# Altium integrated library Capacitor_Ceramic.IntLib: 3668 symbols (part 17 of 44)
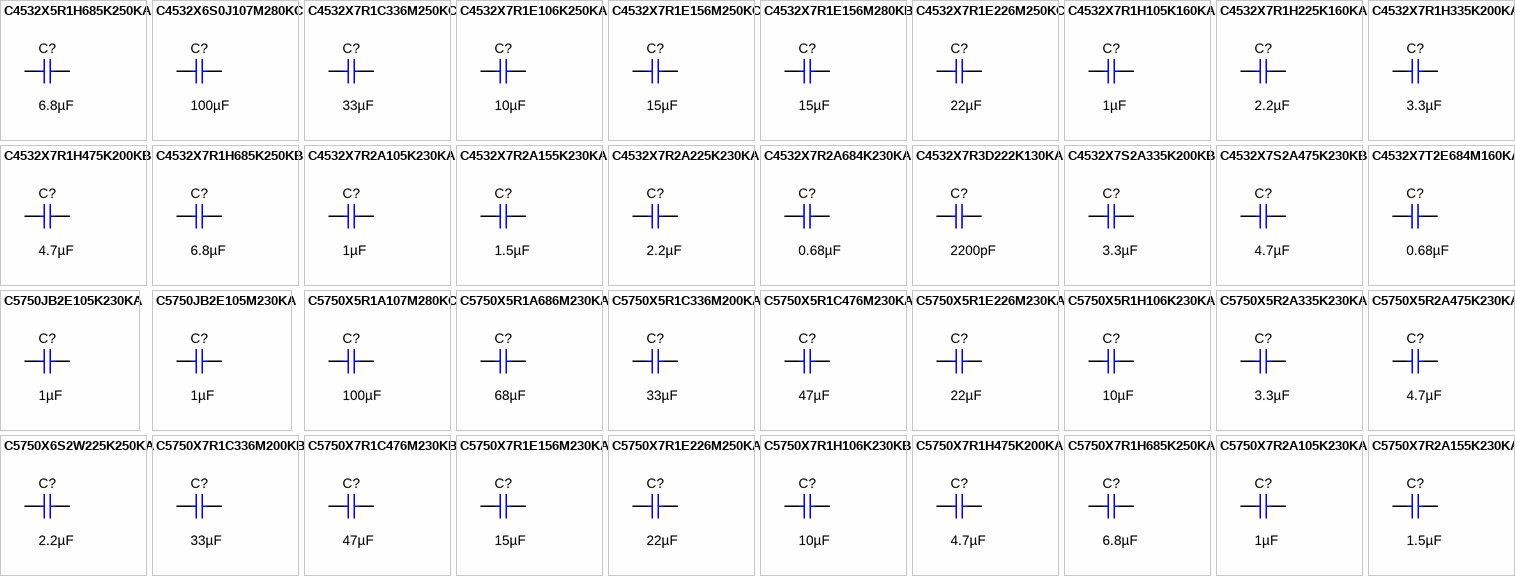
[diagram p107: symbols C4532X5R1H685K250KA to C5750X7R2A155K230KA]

## C4532X7R1E156M280KB
designator C?  ValueDisplayed: 15µF  (hidden comment: C4532X7R1E156M280KB)
CAP, CERM, 15 µF, 25 V,+/- 20%, X7R, 1812; Manufacturer: TDK; Polarized: N; CompType: Capacitor; Value: 15uF; U/M: EA; Cap_F: 0.000015; Tolerance_%: 20; ESR_ohm: 0.002488; Value1: 0.002488 ohm; VDC_V: 25; Value2: 25V; IRMS_A: 4.86254; TaMin_C: -55; TaMax_C: 125; Cap_Case: 1812; SizeArea_mm2: 14.4; SizeAreaWB_mm2: 23.1; SizeX_mm: 4.5; SizeY_mm: 3.2; AEC Category: Q200; Green_Lifecycle: Active; Green_REACh: Passed
signal-integrity model Cap
simulation model Cap
footprint 1812_320
footprint 1812_320M
footprint 1812_320L
pins: 1, 2

## C4532X7R1E226M250KC
designator C?  ValueDisplayed: 22µF  (hidden comment: C4532X7R1E226M250KC)
CAP, CERM, 22 µF, 25 V,+/- 20%, X7R, 1812; Manufacturer: TDK; Polarized: N; CompType: Capacitor; Value: 22uF; U/M: EA; Cap_F: 0.000022; Tolerance_%: 20; ESR_ohm: 0.002434; Value1: 0.002434 ohm; VDC_V: 25; Value2: 25V; IRMS_A: 4.91649; TaMin_C: -55; TaMax_C: 125; Cap_Case: 1812; SizeArea_mm2: 14.4; SizeAreaWB_mm2: 23.1; SizeX_mm: 4.5; SizeY_mm: 3.2; SizeZ_mm: 2.8; AEC Category: Q200; Green_Lifecycle: Active; Green_REACh: Passed
signal-integrity model Cap
simulation model Cap
footprint 1812_280
footprint 1812_280M
footprint 1812_280L
pins: 1, 2

## C4532X7R1H105K160KA
designator C?  ValueDisplayed: 1µF  (hidden comment: C4532X7R1H105K160KA)
CAP, CERM, 1 µF, 50 V,+/- 10%, X7R, 1812; Manufacturer: TDK; Polarized: N; CompType: Capacitor; Value: 1uF; U/M: EA; Cap_F: 0.000001; Tolerance_%: 10; ESR_ohm: 0.007217; Value1: 0.007217 ohm; VDC_V: 50; Value2: 50V; IRMS_A: 2.85919; TaMin_C: -55; TaMax_C: 125; Cap_Case: 1812; SizeArea_mm2: 14.4; SizeAreaWB_mm2: 23.1; SizeX_mm: 4.5; SizeY_mm: 3.2; SizeZ_mm: 1.8; AEC Category: Q200
signal-integrity model Cap
simulation model Cap
footprint 1812_180
pins: 1, 2

## C4532X7R1H225K160KA
designator C?  ValueDisplayed: 2.2µF  (hidden comment: C4532X7R1H225K160KA)
CAP, CERM, 2.2 µF, 50 V,+/- 10%, X7R, 1812; Manufacturer: TDK; Polarized: N; CompType: Capacitor; Value: 2.2uF; U/M: EA; Cap_F: 0.0000022; Tolerance_%: 10; ESR_ohm: 0.00496; Value1: 0.00496 ohm; VDC_V: 50; Value2: 50V; IRMS_A: 3.44575; TaMin_C: -55; TaMax_C: 125; Cap_Case: 1812; SizeArea_mm2: 14.4; SizeAreaWB_mm2: 23.1; SizeX_mm: 4.5; SizeY_mm: 3.2; SizeZ_mm: 1.8; AEC Category: Q200
signal-integrity model Cap
simulation model Cap
footprint 1812_180
pins: 1, 2

## C4532X7R1H335K200KA
designator C?  ValueDisplayed: 3.3µF  (hidden comment: C4532X7R1H335K200KA)
CAP, CERM, 3.3 µF, 50 V,+/- 10%, X7R, 1812; Manufacturer: TDK; Polarized: N; CompType: Capacitor; Value: 3.3uF; U/M: EA; Cap_F: 0.0000033; Tolerance_%: 10; ESR_ohm: 0.004024; Value1: 0.004024 ohm; VDC_V: 50; Value2: 50V; IRMS_A: 3.82481; TaMin_C: -55; TaMax_C: 125; Cap_Case: 1812; SizeArea_mm2: 14.4; SizeAreaWB_mm2: 23.1; SizeX_mm: 4.5; SizeY_mm: 3.2; SizeZ_mm: 2.2; AEC Category: Q200
signal-integrity model Cap
simulation model Cap
footprint 1812_220
footprint 1812_220M
footprint 1812_220L
pins: 1, 2

## C4532X7R1H475K200KB
designator C?  ValueDisplayed: 4.7µF  (hidden comment: C4532X7R1H475K200KB)
CAP, CERM, 4.7 µF, 50 V,+/- 10%, X7R, 1812; Manufacturer: TDK; Polarized: N; CompType: Capacitor; Value: 4.7uF; U/M: EA; Cap_F: 0.0000047; Tolerance_%: 10; ESR_ohm: 0.005172; Value1: 0.005172 ohm; VDC_V: 50; Value2: 50V; IRMS_A: 3.37342; TaMin_C: -55; TaMax_C: 125; Cap_Case: 1812; SizeArea_mm2: 14.4; SizeAreaWB_mm2: 23.1; SizeX_mm: 4.5; SizeY_mm: 3.2; SizeZ_mm: 2.2; AEC Category: Q200; Green_Lifecycle: Active; Green_REACh: Passed
signal-integrity model Cap
simulation model Cap
footprint 1812_220
footprint 1812_220M
footprint 1812_220L
pins: 1, 2

## C4532X7R1H685K250KB
designator C?  ValueDisplayed: 6.8µF  (hidden comment: C4532X7R1H685K250KB)
CAP, CERM, 6.8 µF, 50 V,+/- 10%, X7R, 1812; Manufacturer: TDK; Polarized: N; CompType: Capacitor; Value: 6.8uF; U/M: EA; Cap_F: 0.0000068; Tolerance_%: 10; ESR_ohm: 0.002621; Value1: 0.002621 ohm; VDC_V: 50; Value2: 50V; IRMS_A: 4.73771; TaMin_C: -55; TaMax_C: 125; Cap_Case: 1812; SizeArea_mm2: 14.4; SizeAreaWB_mm2: 23.1; SizeX_mm: 4.5; SizeY_mm: 3.2; SizeZ_mm: 2.8; AEC Category: Q200; Green_Lifecycle: Active; Green_REACh: Passed
signal-integrity model Cap
simulation model Cap
footprint 1812_280
footprint 1812_280M
footprint 1812_280L
pins: 1, 2

## C4532X7R2A105K230KA
designator C?  ValueDisplayed: 1µF  (hidden comment: C4532X7R2A105K230KA)
CAP, CERM, 1 µF, 100 V,+/- 10%, X7R, 1812; Manufacturer: TDK; Polarized: N; CompType: Capacitor; Value: 1uF; U/M: EA; Cap_F: 0.000001; Tolerance_%: 10; ESR_ohm: 0.005865; Value1: 0.005865 ohm; VDC_V: 100; Value2: 100V; IRMS_A: 3.17165; TaMin_C: -55; TaMax_C: 125; Cap_Case: 1812; SizeArea_mm2: 14.4; SizeAreaWB_mm2: 23.1; SizeX_mm: 4.5; SizeY_mm: 3.2; SizeZ_mm: 2.54; AEC Category: Q200
signal-integrity model Cap
simulation model Cap
footprint 1812_254
pins: 1, 2

## C4532X7R2A155K230KA
designator C?  ValueDisplayed: 1.5µF  (hidden comment: C4532X7R2A155K230KA)
CAP, CERM, 1.5 µF, 100 V,+/- 10%, X7R, 1812; Manufacturer: TDK; Polarized: N; CompType: Capacitor; Value: 1.5uF; U/M: EA; Cap_F: 0.0000015; Tolerance_%: 10; ESR_ohm: 0.00449; Value1: 0.00449 ohm; VDC_V: 100; Value2: 100V; IRMS_A: 3.62321; TaMin_C: -55; TaMax_C: 125; Cap_Case: 1812; SizeArea_mm2: 14.4; SizeAreaWB_mm2: 23.1; SizeX_mm: 4.5; SizeY_mm: 3.2; SizeZ_mm: 2.54; AEC Category: Q200
signal-integrity model Cap
simulation model Cap
footprint 1812_254
pins: 1, 2

## C4532X7R2A225K230KA
designator C?  ValueDisplayed: 2.2µF  (hidden comment: C4532X7R2A225K230KA)
CAP, CERM, 2.2 µF, 100 V,+/- 10%, X7R, 1812; Manufacturer: TDK; Polarized: N; CompType: Capacitor; Value: 2.2uF; U/M: EA; Cap_F: 0.0000022; Tolerance_%: 10; ESR_ohm: 0.002981; Value1: 0.002981 ohm; VDC_V: 100; Value2: 100V; IRMS_A: 4.44466; TaMin_C: -55; TaMax_C: 125; Cap_Case: 1812; SizeArea_mm2: 14.4; SizeAreaWB_mm2: 23.1; SizeX_mm: 4.5; SizeY_mm: 3.2; SizeZ_mm: 2.54; AEC Category: Q200; Green_Lifecycle: Active; Green_REACh: Passed
signal-integrity model Cap
simulation model Cap
footprint 1812_254
pins: 1, 2

## C4532X7R2A684K230KA
designator C?  ValueDisplayed: 0.68µF  (hidden comment: C4532X7R2A684K230KA)
CAP, CERM, 0.68 µF, 100 V,+/- 10%, X7R, 1812; Manufacturer: TDK; Polarized: N; CompType: Capacitor; Value: 0.68uF; U/M: EA; Cap_F: 0.00000068; Tolerance_%: 10; ESR_ohm: 0.007113; Value1: 0.007113 ohm; VDC_V: 100; Value2: 100V; IRMS_A: 2.8819; TaMin_C: -55; TaMax_C: 125; Cap_Case: 1812; SizeArea_mm2: 14.4; SizeAreaWB_mm2: 23.1; SizeX_mm: 4.5; SizeY_mm: 3.2; SizeZ_mm: 2.54; AEC Category: Q200
signal-integrity model Cap
simulation model Cap
footprint 1812_254
pins: 1, 2

## C4532X7R3D222K130KA
designator C?  ValueDisplayed: 2200pF  (hidden comment: C4532X7R3D222K130KA)
CAP, CERM, 2200 pF, 2000 V,+/- 10%, X7R, 1812; Manufacturer: TDK; Polarized: N; CompType: Capacitor; Value: 2200pF; U/M: EA; Cap_F: 0.0000000022; Tolerance_%: 10; VDC_V: 2000; Value2: 2000V; TaMin_C: -55; TaMax_C: 125; Cap_Case: 1812; SizeArea_mm2: 14.4; SizeAreaWB_mm2: 23.1; SizeX_mm: 4.5; SizeY_mm: 3.2; SizeZ_mm: 1.35; AEC Category: Q200; Green_Lifecycle: Active; Green_REACh: Passed
signal-integrity model Cap
simulation model Cap
footprint 1812
footprint 1812M
footprint 1812L
footprint 1812_HV
pins: 1, 2

## C4532X7S2A335K200KB
designator C?  ValueDisplayed: 3.3µF  (hidden comment: C4532X7S2A335K200KB)
CAP, CERM, 3.3 µF, 100 V,+/- 10%, X7S, 1812; Manufacturer: TDK; Polarized: N; CompType: Capacitor; Value: 3.3uF; U/M: EA; Cap_F: 0.0000033; Tolerance_%: 10; ESR_ohm: 0.004622; Value1: 0.004622 ohm; VDC_V: 100; Value2: 100V; IRMS_A: 3.5689; TaMin_C: -55; TaMax_C: 125; Cap_Case: 1812; SizeArea_mm2: 14.4; SizeAreaWB_mm2: 23.1; SizeX_mm: 4.5; SizeY_mm: 3.2; SizeZ_mm: 2.2; AEC Category: Q200
signal-integrity model Cap
simulation model Cap
footprint 1812_220
footprint 1812_220M
footprint 1812_220L
pins: 1, 2

## C4532X7S2A475K230KB
designator C?  ValueDisplayed: 4.7µF  (hidden comment: C4532X7S2A475K230KB)
CAP, CERM, 4.7 µF, 100 V,+/- 10%, X7S, 1812; Manufacturer: TDK; Polarized: N; CompType: Capacitor; Value: 4.7uF; U/M: EA; Cap_F: 0.0000047; Tolerance_%: 10; ESR_ohm: 0.00515; Value1: 0.00515 ohm; VDC_V: 100; Value2: 100V; IRMS_A: 3.38056; TaMin_C: -55; TaMax_C: 125; Cap_Case: 1812; SizeArea_mm2: 14.4; SizeAreaWB_mm2: 23.1; SizeX_mm: 4.5; SizeY_mm: 3.2; SizeZ_mm: 2.54; AEC Category: Q200
signal-integrity model Cap
simulation model Cap
footprint 1812_254
pins: 1, 2

## C4532X7T2E684M160KA
designator C?  ValueDisplayed: 0.68µF  (hidden comment: C4532X7T2E684M160KA)
CAP, CERM, 0.68 µF, 250 V,+/- 20%, X7T, 1812; Manufacturer: TDK; Polarized: N; CompType: Capacitor; Value: 0.68uF; U/M: EA; Cap_F: 0.00000068; Tolerance_%: 20; VDC_V: 250; Value2: 250V; TaMin_C: -55; TaMax_C: 125; Cap_Case: 1812; SizeArea_mm2: 14.4; SizeAreaWB_mm2: 23.1; SizeX_mm: 4.5; SizeY_mm: 3.2; SizeZ_mm: 1.35; AEC Category: Q200
signal-integrity model Cap
simulation model Cap
footprint 1812
footprint 1812M
footprint 1812L
footprint 1812_HV
pins: 1, 2

## C5750JB2E105K230KA
designator C?  ValueDisplayed: 1µF  (hidden comment: C5750JB2E105K230KA)
CAP, CERM, 1 µF, 250 V,+/- 10%, JB, 2220; Manufacturer: TDK; Polarized: N; CompType: Capacitor; Value: 1uF; U/M: EA; Cap_F: 0.000001; Tolerance_%: 10; VDC_V: 250; Value2: 250V; TaMin_C: -25; TaMax_C: 85; Cap_Case: 2220; SizeArea_mm2: 28.5; SizeAreaWB_mm2: 53.9; SizeX_mm: 5.7; SizeY_mm: 5; SizeZ_mm: 2.5; AEC Category: Q200; Green_Lifecycle: Not Set; Green_REACh: Incomplete
signal-integrity model Cap
simulation model Cap
footprint 2220_250
footprint 2220_250M
footprint 2220_250L
pins: 1, 2

## C5750JB2E105M230KA
designator C?  ValueDisplayed: 1µF  (hidden comment: C5750JB2E105M230KA)
CAP, CERM, 1 µF, 250 V,+/- 20%, JB, 2220; Manufacturer: TDK; Polarized: N; CompType: Capacitor; Value: 1uF; U/M: EA; Cap_F: 0.000001; Tolerance_%: 20; VDC_V: 250; Value2: 250V; TaMin_C: -25; TaMax_C: 85; Cap_Case: 2220; SizeArea_mm2: 28.5; SizeAreaWB_mm2: 53.9; SizeX_mm: 5.7; SizeY_mm: 5; SizeZ_mm: 2.5; AEC Category: Q200; Green_Lifecycle: Not Set; Green_REACh: Incomplete
signal-integrity model Cap
simulation model Cap
footprint 2220_250
footprint 2220_250M
footprint 2220_250L
pins: 1, 2

## C5750X5R1A107M280KC
designator C?  ValueDisplayed: 100µF  (hidden comment: C5750X5R1A107M280KC)
CAP, CERM, 100 µF, 10 V,+/- 20%, X5R, 2220; Manufacturer: TDK; Polarized: N; CompType: Capacitor; Value: 100uF; U/M: EA; Cap_F: 0.0001; Tolerance_%: 20; ESR_ohm: 0.004556; Value1: 0.004556 ohm; VDC_V: 10; Value2: 10V; IRMS_A: 4.27708; TaMin_C: -55; TaMax_C: 85; Cap_Case: 2220; SizeArea_mm2: 28.5; SizeAreaWB_mm2: 53.9; SizeX_mm: 5.7; SizeY_mm: 5; SizeZ_mm: 3.1; AEC Category: Q200
signal-integrity model Cap
simulation model Cap
footprint 2220_310
footprint 2220_310M
footprint 2220_310L
pins: 1, 2

## C5750X5R1A686M230KA
designator C?  ValueDisplayed: 68µF  (hidden comment: C5750X5R1A686M230KA)
CAP, CERM, 68 µF, 10 V,+/- 20%, X5R, 2220; Manufacturer: TDK; Polarized: N; CompType: Capacitor; Value: 68uF; U/M: EA; Cap_F: 0.000068; Tolerance_%: 20; ESR_ohm: 0.006828; Value1: 0.006828 ohm; VDC_V: 10; Value2: 10V; IRMS_A: 3.49389; TaMin_C: -55; TaMax_C: 85; Cap_Case: 2220; SizeArea_mm2: 28.5; SizeAreaWB_mm2: 53.9; SizeX_mm: 5.7; SizeY_mm: 5; SizeZ_mm: 2.5; AEC Category: Q200
signal-integrity model Cap
simulation model Cap
footprint 2220_250
footprint 2220_250M
footprint 2220_250L
pins: 1, 2

## C5750X5R1C336M200KA
designator C?  ValueDisplayed: 33µF  (hidden comment: C5750X5R1C336M200KA)
CAP, CERM, 33 µF, 16 V,+/- 20%, X5R, 2220; Manufacturer: TDK; Polarized: N; CompType: Capacitor; Value: 33uF; U/M: EA; Cap_F: 0.000033; Tolerance_%: 20; ESR_ohm: 0.002118; Value1: 0.002118 ohm; VDC_V: 16; Value2: 16V; IRMS_A: 6.27268; TaMin_C: -55; TaMax_C: 85; Cap_Case: 2220; SizeArea_mm2: 28.5; SizeAreaWB_mm2: 53.9; SizeX_mm: 5.7; SizeY_mm: 5; SizeZ_mm: 2.2; AEC Category: Q200
signal-integrity model Cap
simulation model Cap
footprint 2220_220
footprint 2220_220M
footprint 2220_220L
pins: 1, 2

## C5750X5R1C476M230KA
designator C?  ValueDisplayed: 47µF  (hidden comment: C5750X5R1C476M230KA)
CAP, CERM, 47 µF, 16 V,+/- 20%, X5R, 2220; Manufacturer: TDK; Polarized: N; CompType: Capacitor; Value: 47uF; U/M: EA; Cap_F: 0.000047; Tolerance_%: 20; ESR_ohm: 0.003162; Value1: 0.003162 ohm; VDC_V: 16; Value2: 16V; IRMS_A: 5.13436; TaMin_C: -55; TaMax_C: 85; Cap_Case: 2220; SizeArea_mm2: 28.5; SizeAreaWB_mm2: 53.9; SizeX_mm: 5.7; SizeY_mm: 5; SizeZ_mm: 2.5; AEC Category: Q200
signal-integrity model Cap
simulation model Cap
footprint 2220_250
footprint 2220_250M
footprint 2220_250L
pins: 1, 2

## C5750X5R1E226M230KA
designator C?  ValueDisplayed: 22µF  (hidden comment: C5750X5R1E226M230KA)
CAP, CERM, 22 µF, 25 V,+/- 20%, X5R, 2220; Manufacturer: TDK; Polarized: N; CompType: Capacitor; Value: 22uF; U/M: EA; Cap_F: 0.000022; Tolerance_%: 20; ESR_ohm: 0.00305; Value1: 0.00305 ohm; VDC_V: 25; Value2: 25V; IRMS_A: 5.22772; TaMin_C: -55; TaMax_C: 85; Cap_Case: 2220; SizeArea_mm2: 28.5; SizeAreaWB_mm2: 53.9; SizeX_mm: 5.7; SizeY_mm: 5; SizeZ_mm: 2.5; AEC Category: Q200
signal-integrity model Cap
simulation model Cap
footprint 2220_250
footprint 2220_250M
footprint 2220_250L
pins: 1, 2

## C5750X5R1H106K230KA
designator C?  ValueDisplayed: 10µF  (hidden comment: C5750X5R1H106K230KA)
CAP, CERM, 10 µF, 50 V,+/- 10%, X5R, 2220; Manufacturer: TDK; Polarized: N; CompType: Capacitor; Value: 10uF; U/M: EA; Cap_F: 0.00001; Tolerance_%: 10; ESR_ohm: 0.002611; Value1: 0.002611 ohm; VDC_V: 50; Value2: 50V; IRMS_A: 5.65008; TaMin_C: -55; TaMax_C: 85; Cap_Case: 2220; SizeArea_mm2: 28.5; SizeAreaWB_mm2: 53.9; SizeX_mm: 5.7; SizeY_mm: 5; SizeZ_mm: 2.5; AEC Category: Q200
signal-integrity model Cap
simulation model Cap
footprint 2220_250
footprint 2220_250M
footprint 2220_250L
pins: 1, 2

## C5750X5R2A335K230KA
designator C?  ValueDisplayed: 3.3µF  (hidden comment: C5750X5R2A335K230KA)
CAP, CERM, 3.3 µF, 100 V,+/- 10%, X5R, 2220; Manufacturer: TDK; Polarized: N; CompType: Capacitor; Value: 3.3uF; U/M: EA; Cap_F: 0.0000033; Tolerance_%: 10; ESR_ohm: 0.002585; Value1: 0.002585 ohm; VDC_V: 100; Value2: 100V; IRMS_A: 5.68031; TaMin_C: -55; TaMax_C: 85; Cap_Case: 2220; SizeArea_mm2: 28.5; SizeAreaWB_mm2: 53.9; SizeX_mm: 5.7; SizeY_mm: 5; SizeZ_mm: 2.5; AEC Category: Q200
signal-integrity model Cap
simulation model Cap
footprint 2220_250
footprint 2220_250M
footprint 2220_250L
pins: 1, 2

## C5750X5R2A475K230KA
designator C?  ValueDisplayed: 4.7µF  (hidden comment: C5750X5R2A475K230KA)
CAP, CERM, 4.7 µF, 100 V,+/- 10%, X5R, 2220; Manufacturer: TDK; Polarized: N; CompType: Capacitor; Value: 4.7uF; U/M: EA; Cap_F: 0.0000047; Tolerance_%: 10; ESR_ohm: 0.002349; Value1: 0.002349 ohm; VDC_V: 100; Value2: 100V; IRMS_A: 5.95718; TaMin_C: -55; TaMax_C: 85; Cap_Case: 2220; SizeArea_mm2: 28.5; SizeAreaWB_mm2: 53.9; SizeX_mm: 5.7; SizeY_mm: 5; SizeZ_mm: 2.5; AEC Category: Q200
signal-integrity model Cap
simulation model Cap
footprint 2220_250
footprint 2220_250M
footprint 2220_250L
pins: 1, 2

## C5750X6S2W225K250KA
designator C?  ValueDisplayed: 2.2µF  (hidden comment: C5750X6S2W225K250KA)
CAP, CERM, 2.2 µF, 450 V,+/- 10%, X6S, 2220; Manufacturer: TDK; Polarized: N; CompType: Capacitor; Value: 2.2uF; U/M: EA; Cap_F: 0.0000022; Tolerance_%: 10; VDC_V: 450; Value2: 450V; TaMin_C: -55; TaMax_C: 105; Cap_Case: 2220; SizeArea_mm2: 28.5; SizeAreaWB_mm2: 53.9; SizeX_mm: 5.7; SizeY_mm: 5; SizeZ_mm: 2.8; AEC Category: Q200; Green_Lifecycle: Not Set; Green_REACh: Incomplete
signal-integrity model Cap
simulation model Cap
footprint 2220_280
footprint 2220_280M
footprint 2220_280L
pins: 1, 2

## C5750X7R1C336M200KB
designator C?  ValueDisplayed: 33µF  (hidden comment: C5750X7R1C336M200KB)
CAP, CERM, 33 µF, 16 V,+/- 20%, X7R, 2220; Manufacturer: TDK; Polarized: N; CompType: Capacitor; Value: 33uF; U/M: EA; Cap_F: 0.000033; Tolerance_%: 20; ESR_ohm: 0.002118; Value1: 0.002118 ohm; VDC_V: 16; Value2: 16V; IRMS_A: 6.27268; TaMin_C: -55; TaMax_C: 125; Cap_Case: 2220; SizeArea_mm2: 28.5; SizeAreaWB_mm2: 53.9; SizeX_mm: 5.7; SizeY_mm: 5; SizeZ_mm: 2.2; AEC Category: Q200
signal-integrity model Cap
simulation model Cap
footprint 2220_220
footprint 2220_220M
footprint 2220_220L
pins: 1, 2

## C5750X7R1C476M230KB
designator C?  ValueDisplayed: 47µF  (hidden comment: C5750X7R1C476M230KB)
CAP, CERM, 47 µF, 16 V,+/- 20%, X7R, 2220; Manufacturer: TDK; Polarized: N; CompType: Capacitor; Value: 47uF; U/M: EA; Cap_F: 0.000047; Tolerance_%: 20; ESR_ohm: 0.003162; Value1: 0.003162 ohm; VDC_V: 16; Value2: 16V; IRMS_A: 5.13436; TaMin_C: -55; TaMax_C: 125; Cap_Case: 2220; SizeArea_mm2: 28.5; SizeAreaWB_mm2: 53.9; SizeX_mm: 5.7; SizeY_mm: 5; SizeZ_mm: 2.5; AEC Category: Q200
signal-integrity model Cap
simulation model Cap
footprint 2220_250
footprint 2220_250M
footprint 2220_250L
pins: 1, 2

## C5750X7R1E156M230KA
designator C?  ValueDisplayed: 15µF  (hidden comment: C5750X7R1E156M230KA)
CAP, CERM, 15 µF, 25 V,+/- 20%, X7R, 2220; Manufacturer: TDK; Polarized: N; CompType: Capacitor; Value: 15uF; U/M: EA; Cap_F: 0.000015; Tolerance_%: 20; ESR_ohm: 0.002725; Value1: 0.002725 ohm; VDC_V: 25; Value2: 25V; IRMS_A: 5.53023; TaMin_C: -55; TaMax_C: 125; Cap_Case: 2220; SizeArea_mm2: 28.5; SizeAreaWB_mm2: 53.9; SizeX_mm: 5.7; SizeY_mm: 5; SizeZ_mm: 2.5; AEC Category: Q200
signal-integrity model Cap
simulation model Cap
footprint 2220_250
footprint 2220_250M
footprint 2220_250L
pins: 1, 2

## C5750X7R1E226M250KA
designator C?  ValueDisplayed: 22µF  (hidden comment: C5750X7R1E226M250KA)
CAP, CERM, 22 µF, 25 V,+/- 20%, X7R, 2220; Manufacturer: TDK; Polarized: N; CompType: Capacitor; Value: 22uF; U/M: EA; Cap_F: 0.000022; Tolerance_%: 20; ESR_ohm: 0.001893; Value1: 0.001893 ohm; VDC_V: 25; Value2: 25V; IRMS_A: 6.63504; TaMin_C: -55; TaMax_C: 125; Cap_Case: 2220; SizeArea_mm2: 28.5; SizeAreaWB_mm2: 53.9; SizeX_mm: 5.7; SizeY_mm: 5; SizeZ_mm: 2.8; AEC Category: Q200
signal-integrity model Cap
simulation model Cap
footprint 2220_280
footprint 2220_280M
footprint 2220_280L
pins: 1, 2

## C5750X7R1H106K230KB
designator C?  ValueDisplayed: 10µF  (hidden comment: C5750X7R1H106K230KB)
CAP, CERM, 10 µF, 50 V,+/- 10%, X7R, 2220; Manufacturer: TDK; Polarized: N; CompType: Capacitor; Value: 10uF; U/M: EA; Cap_F: 0.00001; Tolerance_%: 10; ESR_ohm: 0.002611; Value1: 0.002611 ohm; VDC_V: 50; Value2: 50V; IRMS_A: 5.65008; TaMin_C: -55; TaMax_C: 125; Cap_Case: 2220; SizeArea_mm2: 28.5; SizeAreaWB_mm2: 53.9; SizeX_mm: 5.7; SizeY_mm: 5; SizeZ_mm: 2.5; AEC Category: Q200; Green_Lifecycle: Active; Green_REACh: Passed
signal-integrity model Cap
simulation model Cap
footprint 2220_250
footprint 2220_250M
footprint 2220_250L
pins: 1, 2

## C5750X7R1H475K200KA
designator C?  ValueDisplayed: 4.7µF  (hidden comment: C5750X7R1H475K200KA)
CAP, CERM, 4.7 µF, 50 V,+/- 10%, X7R, 2220; Manufacturer: TDK; Polarized: N; CompType: Capacitor; Value: 4.7uF; U/M: EA; Cap_F: 0.0000047; Tolerance_%: 10; ESR_ohm: 0.003808; Value1: 0.003808 ohm; VDC_V: 50; Value2: 50V; IRMS_A: 4.67908; TaMin_C: -55; TaMax_C: 125; Cap_Case: 2220; SizeArea_mm2: 28.5; SizeAreaWB_mm2: 53.9; SizeX_mm: 5.7; SizeY_mm: 5; SizeZ_mm: 2.2; AEC Category: Q200
signal-integrity model Cap
simulation model Cap
footprint 2220_220
footprint 2220_220M
footprint 2220_220L
pins: 1, 2

## C5750X7R1H685K250KA
designator C?  ValueDisplayed: 6.8µF  (hidden comment: C5750X7R1H685K250KA)
CAP, CERM, 6.8 µF, 50 V,+/- 10%, X7R, 2220; Manufacturer: TDK; Polarized: N; CompType: Capacitor; Value: 6.8uF; U/M: EA; Cap_F: 0.0000068; Tolerance_%: 10; ESR_ohm: 0.002126; Value1: 0.002126 ohm; VDC_V: 50; Value2: 50V; IRMS_A: 6.26198; TaMin_C: -55; TaMax_C: 125; Cap_Case: 2220; SizeArea_mm2: 28.5; SizeAreaWB_mm2: 53.9; SizeX_mm: 5.7; SizeY_mm: 5; SizeZ_mm: 2.8; AEC Category: Q200
signal-integrity model Cap
simulation model Cap
footprint 2220_280
footprint 2220_280M
footprint 2220_280L
pins: 1, 2

## C5750X7R2A105K230KA
designator C?  ValueDisplayed: 1µF  (hidden comment: C5750X7R2A105K230KA)
CAP, CERM, 1 µF, 100 V,+/- 10%, X7R, 2220; Manufacturer: TDK; Polarized: N; CompType: Capacitor; Value: 1uF; U/M: EA; Cap_F: 0.000001; Tolerance_%: 10; ESR_ohm: 0.0056; Value1: 0.0056 ohm; VDC_V: 100; Value2: 100V; IRMS_A: 3.86315; TaMin_C: -55; TaMax_C: 125; Cap_Case: 2220; SizeArea_mm2: 28.5; SizeAreaWB_mm2: 53.9; SizeX_mm: 5.7; SizeY_mm: 5; SizeZ_mm: 2.5; AEC Category: Q200
signal-integrity model Cap
simulation model Cap
footprint 2220_250
footprint 2220_250M
footprint 2220_250L
pins: 1, 2

## C5750X7R2A155K230KA
designator C?  ValueDisplayed: 1.5µF  (hidden comment: C5750X7R2A155K230KA)
CAP, CERM, 1.5 µF, 100 V,+/- 10%, X7R, 2220; Manufacturer: TDK; Polarized: N; CompType: Capacitor; Value: 1.5uF; U/M: EA; Cap_F: 0.0000015; Tolerance_%: 10; ESR_ohm: 0.00441; Value1: 0.00441 ohm; VDC_V: 100; Value2: 100V; IRMS_A: 4.35148; TaMin_C: -55; TaMax_C: 125; Cap_Case: 2220; SizeArea_mm2: 28.5; SizeAreaWB_mm2: 53.9; SizeX_mm: 5.7; SizeY_mm: 5; SizeZ_mm: 2.5; AEC Category: Q200
signal-integrity model Cap
simulation model Cap
footprint 2220_250
footprint 2220_250M
footprint 2220_250L
pins: 1, 2

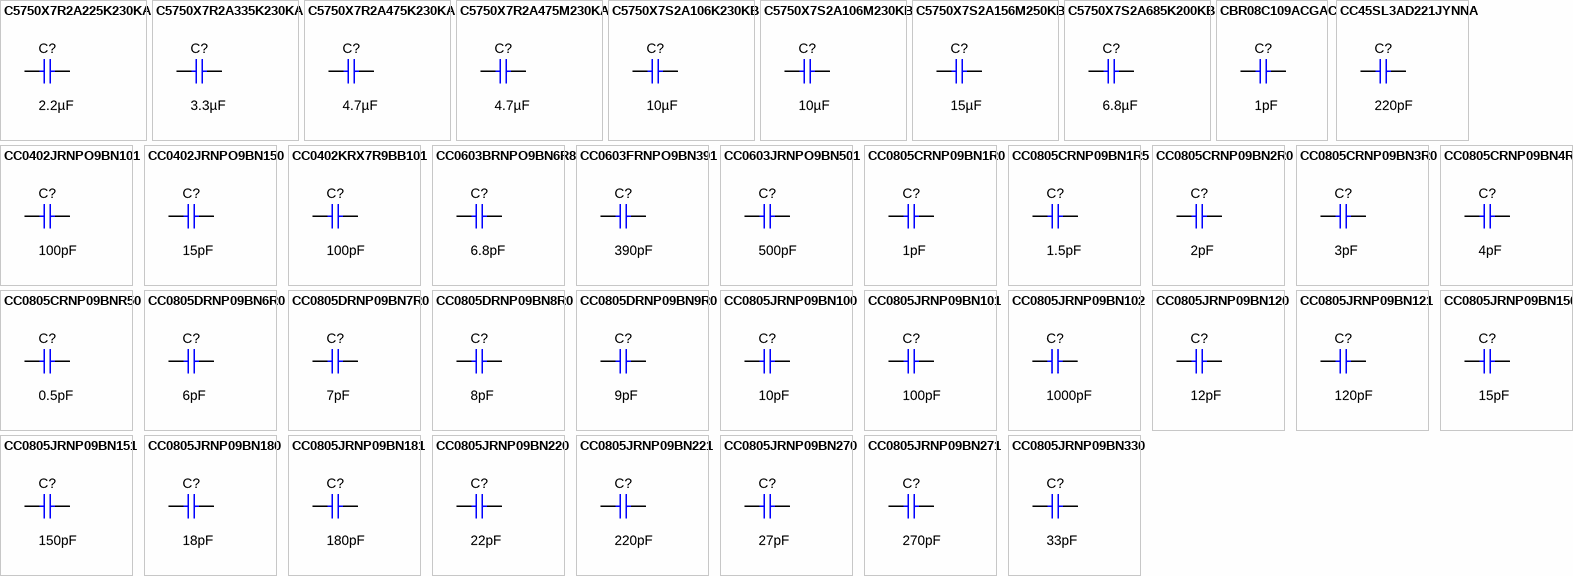
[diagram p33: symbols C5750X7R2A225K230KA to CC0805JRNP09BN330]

## C5750X7R2A225K230KA
designator C?  ValueDisplayed: 2.2µF  (hidden comment: C5750X7R2A225K230KA)
CAP, CERM, 2.2 µF, 100 V,+/- 10%, X7R, 2220; Manufacturer: TDK; Polarized: N; CompType: Capacitor; Value: 2.2uF; U/M: EA; Cap_F: 0.0000022; Tolerance_%: 10; ESR_ohm: 0.002841; Value1: 0.002841 ohm; VDC_V: 100; Value2: 100V; IRMS_A: 5.41912; TaMin_C: -55; TaMax_C: 125; Cap_Case: 2220; SizeArea_mm2: 28.5; SizeAreaWB_mm2: 53.9; SizeX_mm: 5.7; SizeY_mm: 5; SizeZ_mm: 2.5; AEC Category: Q200
signal-integrity model Cap
simulation model Cap
footprint 2220_250
footprint 2220_250M
footprint 2220_250L
pins: 1, 2

## C5750X7R2A335K230KA
designator C?  ValueDisplayed: 3.3µF  (hidden comment: C5750X7R2A335K230KA)
CAP, CERM, 3.3 µF, 100 V,+/- 10%, X7R, 2220; Manufacturer: TDK; Polarized: N; CompType: Capacitor; Value: 3.3uF; U/M: EA; Cap_F: 0.0000033; Tolerance_%: 10; ESR_ohm: 0.002585; Value1: 0.002585 ohm; VDC_V: 100; Value2: 100V; IRMS_A: 5.68031; TaMin_C: -55; TaMax_C: 125; Cap_Case: 2220; SizeArea_mm2: 28.5; SizeAreaWB_mm2: 53.9; SizeX_mm: 5.7; SizeY_mm: 5; SizeZ_mm: 2.5; AEC Category: Q200
signal-integrity model Cap
simulation model Cap
footprint 2220_250
footprint 2220_250M
footprint 2220_250L
pins: 1, 2

## C5750X7R2A475K230KA
designator C?  ValueDisplayed: 4.7µF  (hidden comment: C5750X7R2A475K230KA)
CAP, CERM, 4.7 µF, 100 V,+/- 10%, X7R, 2220; Manufacturer: TDK; Polarized: N; CompType: Capacitor; Value: 4.7uF; U/M: EA; Cap_F: 0.0000047; Tolerance_%: 10; ESR_ohm: 0.002349; Value1: 0.002349 ohm; VDC_V: 100; Value2: 100V; IRMS_A: 5.95718; TaMin_C: -55; TaMax_C: 125; Cap_Case: 2220; SizeArea_mm2: 28.5; SizeAreaWB_mm2: 53.9; SizeX_mm: 5.7; SizeY_mm: 5; SizeZ_mm: 2.5; AEC Category: Q200; Green_Lifecycle: Active; Green_REACh: Passed
signal-integrity model Cap
simulation model Cap
footprint 2220_250
footprint 2220_250M
footprint 2220_250L
pins: 1, 2

## C5750X7R2A475M230KA
designator C?  ValueDisplayed: 4.7µF  (hidden comment: C5750X7R2A475M230KA)
CAP, CERM, 4.7 µF, 100 V,+/- 20%, X7R, 2220; Manufacturer: TDK; Polarized: N; CompType: Capacitor; Value: 4.7uF; U/M: EA; Cap_F: 0.0000047; Tolerance_%: 20; ESR_ohm: 0.0015; Value1: 0.0015 ohm; VDC_V: 100; Value2: 100V; IRMS_A: 5.5; TaMin_C: -55; TaMax_C: 125; Cap_Case: 2220; SizeArea_mm2: 28.5; SizeAreaWB_mm2: 53.9; SizeX_mm: 5.7; SizeY_mm: 5; SizeZ_mm: 2.8; AEC Category: Q200; Green_Lifecycle: Active; Green_REACh: Passed
signal-integrity model Cap
simulation model Cap
footprint 2220_280
footprint 2220_280M
footprint 2220_280L
pins: 1, 2

## C5750X7S2A106K230KB
designator C?  ValueDisplayed: 10µF  (hidden comment: C5750X7S2A106K230KB)
CAP, CERM, 10 µF, 100 V,+/- 10%, X7S, 2220; Manufacturer: TDK; Polarized: N; CompType: Capacitor; Value: 10uF; U/M: EA; Cap_F: 0.00001; Tolerance_%: 10; ESR_ohm: 0.003179; Value1: 0.003179 ohm; VDC_V: 100; Value2: 100V; IRMS_A: 5.11992; TaMin_C: -55; TaMax_C: 125; Cap_Case: 2220; SizeArea_mm2: 28.5; SizeAreaWB_mm2: 53.9; SizeX_mm: 5.7; SizeY_mm: 5; SizeZ_mm: 2.5; AEC Category: Q200
signal-integrity model Cap
simulation model Cap
footprint 2220_250
footprint 2220_250M
footprint 2220_250L
pins: 1, 2

## C5750X7S2A106M230KB
designator C?  ValueDisplayed: 10µF  (hidden comment: C5750X7S2A106M230KB)
CAP, CERM, 10 µF, 100 V,+/- 20%, X7S, 2220; Manufacturer: TDK; Polarized: N; CompType: Capacitor; Value: 10uF; U/M: EA; Cap_F: 0.00001; Tolerance_%: 20; ESR_ohm: 0.005; Value1: 0.005 ohm; VDC_V: 100; Value2: 100V; IRMS_A: 6.45; TaMin_C: -55; TaMax_C: 125; Cap_Case: 2220; SizeArea_mm2: 28.5; SizeAreaWB_mm2: 53.9; SizeX_mm: 5.7; SizeY_mm: 5; SizeZ_mm: 2.5; AEC Category: Q200; Green_Lifecycle: Active; Green_REACh: Passed
signal-integrity model Cap
simulation model Cap
footprint 2220_250
footprint 2220_250M
footprint 2220_250L
pins: 1, 2

## C5750X7S2A156M250KB
designator C?  ValueDisplayed: 15µF  (hidden comment: C5750X7S2A156M250KB)
CAP, CERM, 15 µF, 100 V,+/- 20%, X7S, 2220; Manufacturer: TDK; Polarized: N; CompType: Capacitor; Value: 15uF; U/M: EA; Cap_F: 0.000015; Tolerance_%: 20; ESR_ohm: 0.002642; Value1: 0.002642 ohm; VDC_V: 100; Value2: 100V; IRMS_A: 5.61617; TaMin_C: -55; TaMax_C: 125; Cap_Case: 2220; SizeArea_mm2: 28.5; SizeAreaWB_mm2: 53.9; SizeX_mm: 5.7; SizeY_mm: 5; SizeZ_mm: 2.8; AEC Category: Q200
signal-integrity model Cap
simulation model Cap
footprint 2220_280
footprint 2220_280M
footprint 2220_280L
pins: 1, 2

## C5750X7S2A685K200KB
designator C?  ValueDisplayed: 6.8µF  (hidden comment: C5750X7S2A685K200KB)
CAP, CERM, 6.8 µF, 100 V,+/- 10%, X7S, 2220; Manufacturer: TDK; Polarized: N; CompType: Capacitor; Value: 6.8uF; U/M: EA; Cap_F: 0.0000068; Tolerance_%: 10; ESR_ohm: 0.003492; Value1: 0.003492 ohm; VDC_V: 100; Value2: 100V; IRMS_A: 4.88574; TaMin_C: -55; TaMax_C: 125; Cap_Case: 2220; SizeArea_mm2: 28.5; SizeAreaWB_mm2: 53.9; SizeX_mm: 5.7; SizeY_mm: 5; SizeZ_mm: 2.2; AEC Category: Q200
signal-integrity model Cap
simulation model Cap
footprint 2220_220
footprint 2220_220M
footprint 2220_220L
pins: 1, 2

## CBR08C109ACGAC
designator C?  ValueDisplayed: 1pF  (hidden comment: CBR08C109ACGAC)
CAP, CERM, 1 pF, 500 V,+/- 5%, C0G/NP0, 0805; Manufacturer: Kemet; Polarized: N; CompType: Capacitor; Value: 1pF; U/M: EA; Cap_F: 0.000000000001; Tolerance_%: 5; VDC_V: 500; Value2: 500V; TaMin_C: -55; TaMax_C: 125; Cap_Case: 0805; SizeArea_mm2: 2.5; SizeAreaWB_mm2: 6.75; SizeX_mm: 2; SizeY_mm: 1.25; SizeZ_mm: 1.45; AEC Category: Q200
signal-integrity model Cap
simulation model Cap
footprint 0805_HV
footprint 0805_HV1
footprint 0805
footprint 0805M
footprint 0805L
pins: 1, 2

## CC45SL3AD221JYNNA
designator C?  ValueDisplayed: 220pF  (hidden comment: CC45SL3AD221JYNNA)
CAP, CERM, 220 pF, 1000 V,+/- 5%, SL, D8.5xT5mm; Manufacturer: TDK; Polarized: N; CompType: Capacitor; Value: 220pF; U/M: EA; Cap_F: 0.00000000022; Tolerance_%: 5; VDC_V: 1000; Value2: 1000V; TaMin_C: -25; TaMax_C: 125; Cap_Case: 8.5x5x12.5mm; SizeArea_mm2: 42.5; SizeAreaWB_mm2: 73.5; SizeX_mm: 8.5; SizeZ_mm: 12.5; AEC Category: Q200
signal-integrity model Cap
simulation model Cap
footprint CC45_850x500x1250
pins: 1, 2

## CC0402JRNPO9BN101
designator C?  ValueDisplayed: 100pF  (hidden comment: CC0402JRNPO9BN101)
CAP, CERM, 100 pF, 50 V,+/- 5%, C0G/NP0, 0402; Manufacturer: Yageo America; Polarized: N; CompType: Capacitor; Value: 100pF; U/M: EA; Cap_F: 0.0000000001; Tolerance_%: 5; VDC_V: 50; Value2: 50V; TaMin_C: -55; TaMax_C: 125; Cap_Case: 0402; SizeArea_mm2: 0.5; SizeAreaWB_mm2: 3; SizeX_mm: 1; SizeZ_mm: 0.6; AEC Category: Q200; Green_Lifecycle: Active; Green_REACh: Passed
signal-integrity model Cap
simulation model Cap
footprint 0402
footprint 0402M
footprint 0402L
footprint 0402S
pins: 1, 2

## CC0402JRNPO9BN150
designator C?  ValueDisplayed: 15pF  (hidden comment: CC0402JRNPO9BN150)
CAP, CERM, 15 pF, 50 V,+/- 5%, C0G/NP0, 0402; Manufacturer: Yageo America; Polarized: N; CompType: Capacitor; Value: 15pF; U/M: EA; Cap_F: 0.000000000015; Tolerance_%: 5; VDC_V: 50; Value2: 50V; TaMin_C: -55; TaMax_C: 125; Cap_Case: 0402; SizeArea_mm2: 0.5; SizeAreaWB_mm2: 3; SizeX_mm: 1; SizeZ_mm: 0.6; AEC Category: Q200; Green_Lifecycle: Active; Green_REACh: Passed
signal-integrity model Cap
simulation model Cap
footprint 0402
footprint 0402M
footprint 0402L
footprint 0402S
pins: 1, 2

## CC0402KRX7R9BB101
designator C?  ValueDisplayed: 100pF  (hidden comment: CC0402KRX7R9BB101)
CAP, CERM, 100 pF, 50 V,+/- 10%, X7R, 0402; Manufacturer: Yageo America; Polarized: N; CompType: Capacitor; Value: 100pF; U/M: EA; Cap_F: 0.0000000001; Tolerance_%: 10; VDC_V: 50; Value2: 50V; TaMin_C: -55; TaMax_C: 125; Cap_Case: 0402; SizeArea_mm2: 0.5; SizeAreaWB_mm2: 3; SizeX_mm: 1; SizeZ_mm: 0.6; AEC Category: Q200; Green_Lifecycle: Active; Green_REACh: Passed
signal-integrity model Cap
simulation model Cap
footprint 0402
footprint 0402M
footprint 0402L
footprint 0402S
pins: 1, 2

## CC0603BRNPO9BN6R8
designator C?  ValueDisplayed: 6.8pF  (hidden comment: CC0603BRNPO9BN6R8)
CAP, CERM, 6.8 pF, 50 V,+/- 2%, C0G/NP0, 0603; Manufacturer: Yageo America; Polarized: N; CompType: Capacitor; Value: 6.8pF; U/M: EA; Cap_F: 0.0000000000068; Tolerance_%: 2; VDC_V: 50; Value2: 50V; TaMin_C: -55; TaMax_C: 125; Cap_Case: 0603; SizeArea_mm2: 1.28; SizeAreaWB_mm2: 4.68; SizeX_mm: 1.6; SizeY_mm: 0.8; SizeZ_mm: 1; AEC Category: Q200
signal-integrity model Cap
simulation model Cap
footprint 0603
footprint 0603M
footprint 0603L
footprint 0603_HV
footprint 0603S
pins: 1, 2

## CC0603FRNPO9BN391
designator C?  ValueDisplayed: 390pF  (hidden comment: CC0603FRNPO9BN391)
CAP, CERM, 390 pF, 50 V,+/- 1%, C0G/NP0, 0603; Manufacturer: Yageo America; Polarized: N; CompType: Capacitor; Value: 390pF; U/M: EA; Cap_F: 0.00000000039; Tolerance_%: 1; VDC_V: 50; Value2: 50V; TaMin_C: -55; TaMax_C: 125; Cap_Case: 0603; SizeArea_mm2: 1.28; SizeAreaWB_mm2: 4.68; SizeX_mm: 1.6; SizeY_mm: 0.8; AEC Category: Q200
signal-integrity model Cap
simulation model Cap
footprint 0603
footprint 0603M
footprint 0603L
footprint 0603_HV
footprint 0603S
pins: 1, 2

## CC0603JRNPO9BN501
designator C?  ValueDisplayed: 500pF  (hidden comment: CC0603JRNPO9BN501)
CAP, CERM, 500 pF, 50 V,+/- 5%, C0G/NP0, 0603; Manufacturer: Yageo America; Polarized: N; CompType: Capacitor; Value: 500pF; U/M: EA; Cap_F: 5e-010; Tolerance_%: 5; VDC_V: 50; Value2: 50V; TaMin_C: -55; TaMax_C: 125; Cap_Case: 0603; SizeArea_mm2: 1.28; SizeAreaWB_mm2: 4.68; SizeX_mm: 1.6; SizeY_mm: 0.8; SizeZ_mm: 1; AEC Category: Q200
signal-integrity model Cap
simulation model Cap
footprint 0603
footprint 0603M
footprint 0603L
footprint 0603_HV
footprint 0603S
pins: 1, 2

## CC0805CRNP09BN1R0
designator C?  ValueDisplayed: 1pF  (hidden comment: CC0805CRNP09BN1R0)
CAP, CERM, 1 pF, 50 V,+/- 25%, C0G/NP0, 0805; Manufacturer: Yageo America; Polarized: N; CompType: Capacitor; Value: 1pF; U/M: EA; Cap_F: 0.000000000001; Tolerance_%: 25; VDC_V: 50; Value2: 50V; TaMin_C: -55; TaMax_C: 125; Cap_Case: 0805; SizeArea_mm2: 2.5; SizeAreaWB_mm2: 6.75; SizeX_mm: 2; SizeY_mm: 1.25; SizeZ_mm: 1.45; AEC Category: Q200
signal-integrity model Cap
simulation model Cap
footprint 0805_HV
footprint 0805_HV1
footprint 0805
footprint 0805M
footprint 0805L
pins: 1, 2

## CC0805CRNP09BN1R5
designator C?  ValueDisplayed: 1.5pF  (hidden comment: CC0805CRNP09BN1R5)
CAP, CERM, 1.5 pF, 50 V,+/- 17%, C0G/NP0, 0805; Manufacturer: Yageo America; Polarized: N; CompType: Capacitor; Value: 1.5pF; U/M: EA; Cap_F: 0.0000000000015; Tolerance_%: 17; VDC_V: 50; Value2: 50V; TaMin_C: -55; TaMax_C: 125; Cap_Case: 0805; SizeArea_mm2: 2.5; SizeAreaWB_mm2: 6.75; SizeX_mm: 2; SizeY_mm: 1.25; SizeZ_mm: 1.45; AEC Category: Q200
signal-integrity model Cap
simulation model Cap
footprint 0805_HV
footprint 0805_HV1
footprint 0805
footprint 0805M
footprint 0805L
pins: 1, 2

## CC0805CRNP09BN2R0
designator C?  ValueDisplayed: 2pF  (hidden comment: CC0805CRNP09BN2R0)
CAP, CERM, 2 pF, 50 V,+/- 13%, C0G/NP0, 0805; Manufacturer: Yageo America; Polarized: N; CompType: Capacitor; Value: 2pF; U/M: EA; Cap_F: 0.000000000002; Tolerance_%: 13; VDC_V: 50; Value2: 50V; TaMin_C: -55; TaMax_C: 125; Cap_Case: 0805; SizeArea_mm2: 2.5; SizeAreaWB_mm2: 6.75; SizeX_mm: 2; SizeY_mm: 1.25; SizeZ_mm: 1.45; AEC Category: Q200
signal-integrity model Cap
simulation model Cap
footprint 0805_HV
footprint 0805_HV1
footprint 0805
footprint 0805M
footprint 0805L
pins: 1, 2

## CC0805CRNP09BN3R0
designator C?  ValueDisplayed: 3pF  (hidden comment: CC0805CRNP09BN3R0)
CAP, CERM, 3 pF, 50 V,+/- 8%, C0G/NP0, 0805; Manufacturer: Yageo America; Polarized: N; CompType: Capacitor; Value: 3pF; U/M: EA; Cap_F: 0.000000000003; Tolerance_%: 8; VDC_V: 50; Value2: 50V; TaMin_C: -55; TaMax_C: 125; Cap_Case: 0805; SizeArea_mm2: 2.5; SizeAreaWB_mm2: 6.75; SizeX_mm: 2; SizeY_mm: 1.25; SizeZ_mm: 1.45; AEC Category: Q200
signal-integrity model Cap
simulation model Cap
footprint 0805_HV
footprint 0805_HV1
footprint 0805
footprint 0805M
footprint 0805L
pins: 1, 2

## CC0805CRNP09BN4R0
designator C?  ValueDisplayed: 4pF  (hidden comment: CC0805CRNP09BN4R0)
CAP, CERM, 4 pF, 50 V,+/- 6%, C0G/NP0, 0805; Manufacturer: Yageo America; Polarized: N; CompType: Capacitor; Value: 4pF; U/M: EA; Cap_F: 0.000000000004; Tolerance_%: 6; VDC_V: 50; Value2: 50V; TaMin_C: -55; TaMax_C: 125; Cap_Case: 0805; SizeArea_mm2: 2.5; SizeAreaWB_mm2: 6.75; SizeX_mm: 2; SizeY_mm: 1.25; SizeZ_mm: 1.45; AEC Category: Q200
signal-integrity model Cap
simulation model Cap
footprint 0805_HV
footprint 0805_HV1
footprint 0805
footprint 0805M
footprint 0805L
pins: 1, 2

## CC0805CRNP09BNR50
designator C?  ValueDisplayed: 0.5pF  (hidden comment: CC0805CRNP09BNR50)
CAP, CERM, 0.5 pF, 50 V,+/- 50%, C0G/NP0, 0805; Manufacturer: Yageo America; Polarized: N; CompType: Capacitor; Value: 0.5pF; U/M: EA; Cap_F: 0.0000000000005; Tolerance_%: 50; Value2: 50V; TaMin_C: -55; TaMax_C: 125; Cap_Case: 0805; SizeArea_mm2: 2.5; SizeAreaWB_mm2: 6.75; SizeX_mm: 2; SizeY_mm: 1.25; SizeZ_mm: 1.45; AEC Category: Q200
signal-integrity model Cap
simulation model Cap
footprint 0805_HV
footprint 0805_HV1
footprint 0805
footprint 0805M
footprint 0805L
pins: 1, 2

## CC0805DRNP09BN6R0
designator C?  ValueDisplayed: 6pF  (hidden comment: CC0805DRNP09BN6R0)
CAP, CERM, 6 pF, 50 V,+/- 8%, C0G/NP0, 0805; Manufacturer: Yageo America; Polarized: N; CompType: Capacitor; Value: 6pF; U/M: EA; Cap_F: 0.000000000006; Tolerance_%: 8; VDC_V: 50; Value2: 50V; TaMin_C: -55; TaMax_C: 125; Cap_Case: 0805; SizeArea_mm2: 2.5; SizeAreaWB_mm2: 6.75; SizeX_mm: 2; SizeY_mm: 1.25; SizeZ_mm: 1.45; AEC Category: Q200
signal-integrity model Cap
simulation model Cap
footprint 0805_HV
footprint 0805_HV1
footprint 0805
footprint 0805M
footprint 0805L
pins: 1, 2

## CC0805DRNP09BN7R0
designator C?  ValueDisplayed: 7pF  (hidden comment: CC0805DRNP09BN7R0)
CAP, CERM, 7 pF, 50 V,+/- 7%, C0G/NP0, 0805; Manufacturer: Yageo America; Polarized: N; CompType: Capacitor; Value: 7pF; U/M: EA; Cap_F: 0.000000000007; Tolerance_%: 7; VDC_V: 50; Value2: 50V; TaMin_C: -55; TaMax_C: 125; Cap_Case: 0805; SizeArea_mm2: 2.5; SizeAreaWB_mm2: 6.75; SizeX_mm: 2; SizeY_mm: 1.25; SizeZ_mm: 1.45; AEC Category: Q200
signal-integrity model Cap
simulation model Cap
footprint 0805_HV
footprint 0805_HV1
footprint 0805
footprint 0805M
footprint 0805L
pins: 1, 2

## CC0805DRNP09BN8R0
designator C?  ValueDisplayed: 8pF  (hidden comment: CC0805DRNP09BN8R0)
CAP, CERM, 8 pF, 50 V,+/- 6%, C0G/NP0, 0805; Manufacturer: Yageo America; Polarized: N; CompType: Capacitor; Value: 8pF; U/M: EA; Cap_F: 0.000000000008; Tolerance_%: 6; VDC_V: 50; Value2: 50V; TaMin_C: -55; TaMax_C: 125; Cap_Case: 0805; SizeArea_mm2: 2.5; SizeAreaWB_mm2: 6.75; SizeX_mm: 2; SizeY_mm: 1.25; SizeZ_mm: 1.45; AEC Category: Q200
signal-integrity model Cap
simulation model Cap
footprint 0805_HV
footprint 0805_HV1
footprint 0805
footprint 0805M
footprint 0805L
pins: 1, 2

## CC0805DRNP09BN9R0
designator C?  ValueDisplayed: 9pF  (hidden comment: CC0805DRNP09BN9R0)
CAP, CERM, 9 pF, 50 V,+/- 6%, C0G/NP0, 0805; Manufacturer: Yageo America; Polarized: N; CompType: Capacitor; Value: 9pF; U/M: EA; Cap_F: 0.000000000009; Tolerance_%: 6; VDC_V: 50; Value2: 50V; TaMin_C: -55; TaMax_C: 125; Cap_Case: 0805; SizeArea_mm2: 2.5; SizeAreaWB_mm2: 6.75; SizeX_mm: 2; SizeY_mm: 1.25; SizeZ_mm: 1.45; AEC Category: Q200
signal-integrity model Cap
simulation model Cap
footprint 0805_HV
footprint 0805_HV1
footprint 0805
footprint 0805M
footprint 0805L
pins: 1, 2

## CC0805JRNP09BN100
designator C?  ValueDisplayed: 10pF  (hidden comment: CC0805JRNP09BN100)
CAP, CERM, 10 pF, 50 V,+/- 5%, C0G/NP0, 0805; Manufacturer: Yageo America; Polarized: N; CompType: Capacitor; Value: 10pF; U/M: EA; Cap_F: 0.00000000001; Tolerance_%: 5; VDC_V: 50; Value2: 50V; TaMin_C: -55; TaMax_C: 125; Cap_Case: 0805; SizeArea_mm2: 2.5; SizeAreaWB_mm2: 6.75; SizeX_mm: 2; SizeY_mm: 1.25; SizeZ_mm: 1.45; AEC Category: Q200
signal-integrity model Cap
simulation model Cap
footprint 0805_HV
footprint 0805_HV1
footprint 0805
footprint 0805M
footprint 0805L
pins: 1, 2

## CC0805JRNP09BN101
designator C?  ValueDisplayed: 100pF  (hidden comment: CC0805JRNP09BN101)
CAP, CERM, 100 pF, 50 V,+/- 5%, C0G/NP0, 0805; Manufacturer: Yageo America; Polarized: N; CompType: Capacitor; Value: 100pF; U/M: EA; Cap_F: 0.0000000001; Tolerance_%: 5; VDC_V: 50; Value2: 50V; TaMin_C: -55; TaMax_C: 125; Cap_Case: 0805; SizeArea_mm2: 2.5; SizeAreaWB_mm2: 6.75; SizeX_mm: 2; SizeY_mm: 1.25; SizeZ_mm: 1.45; AEC Category: Q200
signal-integrity model Cap
simulation model Cap
footprint 0805_HV
footprint 0805_HV1
footprint 0805
footprint 0805M
footprint 0805L
pins: 1, 2

## CC0805JRNP09BN102
designator C?  ValueDisplayed: 1000pF  (hidden comment: CC0805JRNP09BN102)
CAP, CERM, 1000 pF, 50 V,+/- 5%, C0G/NP0, 0805; Manufacturer: Yageo America; Polarized: N; CompType: Capacitor; Value: 1000pF; U/M: EA; Cap_F: 0.000000001; Tolerance_%: 5; VDC_V: 50; Value2: 50V; TaMin_C: -55; TaMax_C: 125; Cap_Case: 0805; SizeArea_mm2: 2.5; SizeAreaWB_mm2: 6.75; SizeX_mm: 2; SizeY_mm: 1.25; SizeZ_mm: 1.45; AEC Category: Q200
signal-integrity model Cap
simulation model Cap
footprint 0805_HV
footprint 0805_HV1
footprint 0805
footprint 0805M
footprint 0805L
pins: 1, 2

## CC0805JRNP09BN120
designator C?  ValueDisplayed: 12pF  (hidden comment: CC0805JRNP09BN120)
CAP, CERM, 12 pF, 50 V,+/- 5%, C0G/NP0, 0805; Manufacturer: Yageo America; Polarized: N; CompType: Capacitor; Value: 12pF; U/M: EA; Cap_F: 0.000000000012; Tolerance_%: 5; VDC_V: 50; Value2: 50V; TaMin_C: -55; TaMax_C: 125; Cap_Case: 0805; SizeArea_mm2: 2.5; SizeAreaWB_mm2: 6.75; SizeX_mm: 2; SizeY_mm: 1.25; SizeZ_mm: 1.45; AEC Category: Q200
signal-integrity model Cap
simulation model Cap
footprint 0805_HV
footprint 0805_HV1
footprint 0805
footprint 0805M
footprint 0805L
pins: 1, 2

## CC0805JRNP09BN121
designator C?  ValueDisplayed: 120pF  (hidden comment: CC0805JRNP09BN121)
CAP, CERM, 120 pF, 50 V,+/- 5%, C0G/NP0, 0805; Manufacturer: Yageo America; Polarized: N; CompType: Capacitor; Value: 120pF; U/M: EA; Cap_F: 0.00000000012; Tolerance_%: 5; VDC_V: 50; Value2: 50V; TaMin_C: -55; TaMax_C: 125; Cap_Case: 0805; SizeArea_mm2: 2.5; SizeAreaWB_mm2: 6.75; SizeX_mm: 2; SizeY_mm: 1.25; SizeZ_mm: 1.45; AEC Category: Q200
signal-integrity model Cap
simulation model Cap
footprint 0805_HV
footprint 0805_HV1
footprint 0805
footprint 0805M
footprint 0805L
pins: 1, 2

## CC0805JRNP09BN150
designator C?  ValueDisplayed: 15pF  (hidden comment: CC0805JRNP09BN150)
CAP, CERM, 15 pF, 50 V,+/- 5%, C0G/NP0, 0805; Manufacturer: Yageo America; Polarized: N; CompType: Capacitor; Value: 15pF; U/M: EA; Cap_F: 0.000000000015; Tolerance_%: 5; VDC_V: 50; Value2: 50V; TaMin_C: -55; TaMax_C: 125; Cap_Case: 0805; SizeArea_mm2: 2.5; SizeAreaWB_mm2: 6.75; SizeX_mm: 2; SizeY_mm: 1.25; SizeZ_mm: 1.45; AEC Category: Q200
signal-integrity model Cap
simulation model Cap
footprint 0805_HV
footprint 0805_HV1
footprint 0805
footprint 0805M
footprint 0805L
pins: 1, 2

## CC0805JRNP09BN151
designator C?  ValueDisplayed: 150pF  (hidden comment: CC0805JRNP09BN151)
CAP, CERM, 150 pF, 50 V,+/- 5%, C0G/NP0, 0805; Manufacturer: Yageo America; Polarized: N; CompType: Capacitor; Value: 150pF; U/M: EA; Cap_F: 0.00000000015; Tolerance_%: 5; VDC_V: 50; Value2: 50V; TaMin_C: -55; TaMax_C: 125; Cap_Case: 0805; SizeArea_mm2: 2.5; SizeAreaWB_mm2: 6.75; SizeX_mm: 2; SizeY_mm: 1.25; SizeZ_mm: 1.45; AEC Category: Q200
signal-integrity model Cap
simulation model Cap
footprint 0805_HV
footprint 0805_HV1
footprint 0805
footprint 0805M
footprint 0805L
pins: 1, 2

## CC0805JRNP09BN180
designator C?  ValueDisplayed: 18pF  (hidden comment: CC0805JRNP09BN180)
CAP, CERM, 18 pF, 50 V,+/- 5%, C0G/NP0, 0805; Manufacturer: Yageo America; Polarized: N; CompType: Capacitor; Value: 18pF; U/M: EA; Cap_F: 0.000000000018; Tolerance_%: 5; VDC_V: 50; Value2: 50V; TaMin_C: -55; TaMax_C: 125; Cap_Case: 0805; SizeArea_mm2: 2.5; SizeAreaWB_mm2: 6.75; SizeX_mm: 2; SizeY_mm: 1.25; SizeZ_mm: 1.45; AEC Category: Q200
signal-integrity model Cap
simulation model Cap
footprint 0805_HV
footprint 0805_HV1
footprint 0805
footprint 0805M
footprint 0805L
pins: 1, 2

## CC0805JRNP09BN181
designator C?  ValueDisplayed: 180pF  (hidden comment: CC0805JRNP09BN181)
CAP, CERM, 180 pF, 50 V,+/- 5%, C0G/NP0, 0805; Manufacturer: Yageo America; Polarized: N; CompType: Capacitor; Value: 180pF; U/M: EA; Cap_F: 0.00000000018; Tolerance_%: 5; VDC_V: 50; Value2: 50V; TaMin_C: -55; TaMax_C: 125; Cap_Case: 0805; SizeArea_mm2: 2.5; SizeAreaWB_mm2: 6.75; SizeX_mm: 2; SizeY_mm: 1.25; SizeZ_mm: 1.45; AEC Category: Q200
signal-integrity model Cap
simulation model Cap
footprint 0805_HV
footprint 0805_HV1
footprint 0805
footprint 0805M
footprint 0805L
pins: 1, 2

## CC0805JRNP09BN220
designator C?  ValueDisplayed: 22pF  (hidden comment: CC0805JRNP09BN220)
CAP, CERM, 22 pF, 50 V,+/- 5%, C0G/NP0, 0805; Manufacturer: Yageo America; Polarized: N; CompType: Capacitor; Value: 22pF; U/M: EA; Cap_F: 0.000000000022; Tolerance_%: 5; VDC_V: 50; Value2: 50V; TaMin_C: -55; TaMax_C: 125; Cap_Case: 0805; SizeArea_mm2: 2.5; SizeAreaWB_mm2: 6.75; SizeX_mm: 2; SizeY_mm: 1.25; SizeZ_mm: 1.45; AEC Category: Q200
signal-integrity model Cap
simulation model Cap
footprint 0805_HV
footprint 0805_HV1
footprint 0805
footprint 0805M
footprint 0805L
pins: 1, 2

## CC0805JRNP09BN221
designator C?  ValueDisplayed: 220pF  (hidden comment: CC0805JRNP09BN221)
CAP, CERM, 220 pF, 50 V,+/- 5%, C0G/NP0, 0805; Manufacturer: Yageo America; Polarized: N; CompType: Capacitor; Value: 220pF; U/M: EA; Cap_F: 0.00000000022; Tolerance_%: 5; VDC_V: 50; Value2: 50V; TaMin_C: -55; TaMax_C: 125; Cap_Case: 0805; SizeArea_mm2: 2.5; SizeAreaWB_mm2: 6.75; SizeX_mm: 2; SizeY_mm: 1.25; SizeZ_mm: 1.45; AEC Category: Q200
signal-integrity model Cap
simulation model Cap
footprint 0805_HV
footprint 0805_HV1
footprint 0805
footprint 0805M
footprint 0805L
pins: 1, 2

## CC0805JRNP09BN270
designator C?  ValueDisplayed: 27pF  (hidden comment: CC0805JRNP09BN270)
CAP, CERM, 27 pF, 50 V,+/- 5%, C0G/NP0, 0805; Manufacturer: Yageo America; Polarized: N; CompType: Capacitor; Value: 27pF; U/M: EA; Cap_F: 0.000000000027; Tolerance_%: 5; VDC_V: 50; Value2: 50V; TaMin_C: -55; TaMax_C: 125; Cap_Case: 0805; SizeArea_mm2: 2.5; SizeAreaWB_mm2: 6.75; SizeX_mm: 2; SizeY_mm: 1.25; SizeZ_mm: 1.45; AEC Category: Q200
signal-integrity model Cap
simulation model Cap
footprint 0805_HV
footprint 0805_HV1
footprint 0805
footprint 0805M
footprint 0805L
pins: 1, 2

## CC0805JRNP09BN271
designator C?  ValueDisplayed: 270pF  (hidden comment: CC0805JRNP09BN271)
CAP, CERM, 270 pF, 50 V,+/- 5%, C0G/NP0, 0805; Manufacturer: Yageo America; Polarized: N; CompType: Capacitor; Value: 270pF; U/M: EA; Cap_F: 0.00000000027; Tolerance_%: 5; VDC_V: 50; Value2: 50V; TaMin_C: -55; TaMax_C: 125; Cap_Case: 0805; SizeArea_mm2: 2.5; SizeAreaWB_mm2: 6.75; SizeX_mm: 2; SizeY_mm: 1.25; SizeZ_mm: 1.45; AEC Category: Q200
signal-integrity model Cap
simulation model Cap
footprint 0805_HV
footprint 0805_HV1
footprint 0805
footprint 0805M
footprint 0805L
pins: 1, 2

## CC0805JRNP09BN330
designator C?  ValueDisplayed: 33pF  (hidden comment: CC0805JRNP09BN330)
CAP, CERM, 33 pF, 50 V,+/- 5%, C0G/NP0, 0805; Manufacturer: Yageo America; Polarized: N; CompType: Capacitor; Value: 33pF; U/M: EA; Cap_F: 0.000000000033; Tolerance_%: 5; VDC_V: 50; Value2: 50V; TaMin_C: -55; TaMax_C: 125; Cap_Case: 0805; SizeArea_mm2: 2.5; SizeAreaWB_mm2: 6.75; SizeX_mm: 2; SizeY_mm: 1.25; SizeZ_mm: 1.45; AEC Category: Q200; Green_Lifecycle: Active; Green_REACh: Passed
signal-integrity model Cap
simulation model Cap
footprint 0805_HV
footprint 0805_HV1
footprint 0805
footprint 0805M
footprint 0805L
pins: 1, 2

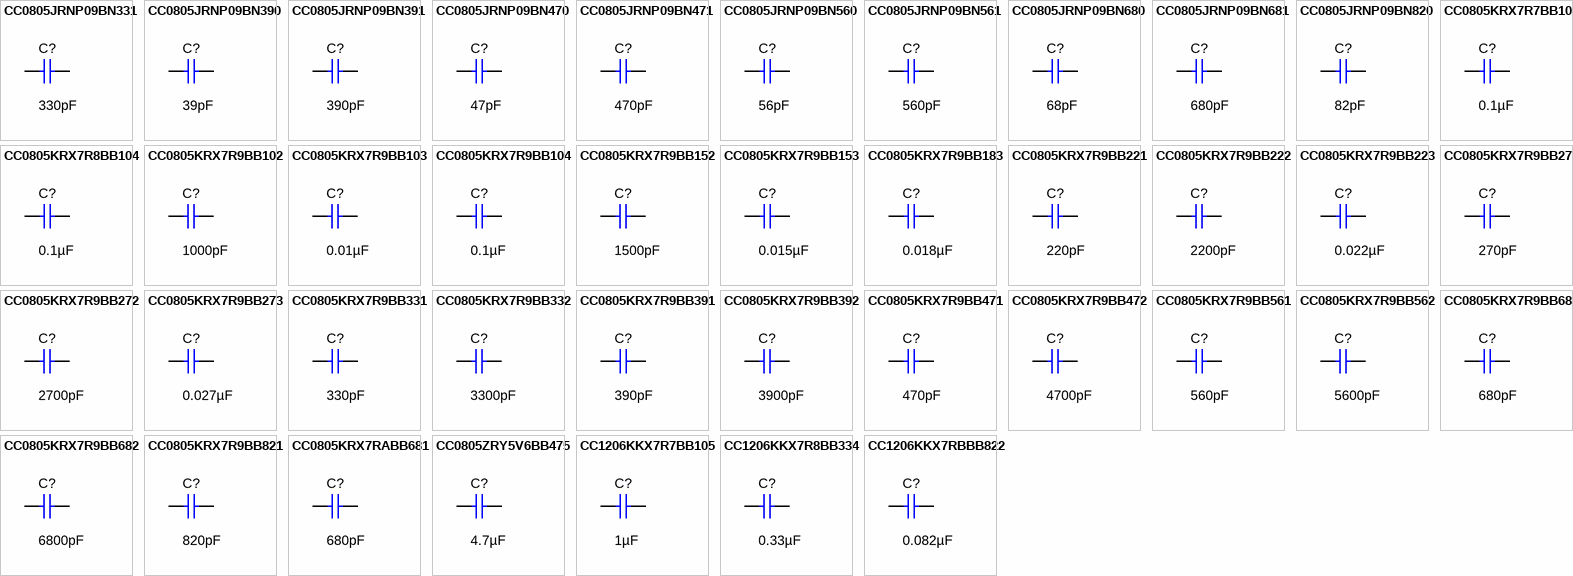
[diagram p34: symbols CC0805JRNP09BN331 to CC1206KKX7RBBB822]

## CC0805JRNP09BN331
designator C?  ValueDisplayed: 330pF  (hidden comment: CC0805JRNP09BN331)
CAP, CERM, 330 pF, 50 V,+/- 5%, C0G/NP0, 0805; Manufacturer: Yageo America; Polarized: N; CompType: Capacitor; Value: 330pF; U/M: EA; Cap_F: 0.00000000033; Tolerance_%: 5; VDC_V: 50; Value2: 50V; TaMin_C: -55; TaMax_C: 125; Cap_Case: 0805; SizeArea_mm2: 2.5; SizeAreaWB_mm2: 6.75; SizeX_mm: 2; SizeY_mm: 1.25; SizeZ_mm: 1.45; AEC Category: Q200
signal-integrity model Cap
simulation model Cap
footprint 0805_HV
footprint 0805_HV1
footprint 0805
footprint 0805M
footprint 0805L
pins: 1, 2

## CC0805JRNP09BN390
designator C?  ValueDisplayed: 39pF  (hidden comment: CC0805JRNP09BN390)
CAP, CERM, 39 pF, 50 V,+/- 5%, C0G/NP0, 0805; Manufacturer: Yageo America; Polarized: N; CompType: Capacitor; Value: 39pF; U/M: EA; Cap_F: 0.000000000039; Tolerance_%: 5; VDC_V: 50; Value2: 50V; TaMin_C: -55; TaMax_C: 125; Cap_Case: 0805; SizeArea_mm2: 2.5; SizeAreaWB_mm2: 6.75; SizeX_mm: 2; SizeY_mm: 1.25; SizeZ_mm: 1.45; AEC Category: Q200
signal-integrity model Cap
simulation model Cap
footprint 0805_HV
footprint 0805_HV1
footprint 0805
footprint 0805M
footprint 0805L
pins: 1, 2

## CC0805JRNP09BN391
designator C?  ValueDisplayed: 390pF  (hidden comment: CC0805JRNP09BN391)
CAP, CERM, 390 pF, 50 V,+/- 5%, C0G/NP0, 0805; Manufacturer: Yageo America; Polarized: N; CompType: Capacitor; Value: 390pF; U/M: EA; Cap_F: 0.00000000039; Tolerance_%: 5; VDC_V: 50; Value2: 50V; TaMin_C: -55; TaMax_C: 125; Cap_Case: 0805; SizeArea_mm2: 2.5; SizeAreaWB_mm2: 6.75; SizeX_mm: 2; SizeY_mm: 1.25; SizeZ_mm: 1.45; AEC Category: Q200
signal-integrity model Cap
simulation model Cap
footprint 0805_HV
footprint 0805_HV1
footprint 0805
footprint 0805M
footprint 0805L
pins: 1, 2

## CC0805JRNP09BN470
designator C?  ValueDisplayed: 47pF  (hidden comment: CC0805JRNP09BN470)
CAP, CERM, 47 pF, 50 V,+/- 5%, C0G/NP0, 0805; Manufacturer: Yageo America; Polarized: N; CompType: Capacitor; Value: 47pF; U/M: EA; Cap_F: 0.000000000047; Tolerance_%: 5; VDC_V: 50; Value2: 50V; TaMin_C: -55; TaMax_C: 125; Cap_Case: 0805; SizeArea_mm2: 2.5; SizeAreaWB_mm2: 6.75; SizeX_mm: 2; SizeY_mm: 1.25; SizeZ_mm: 1.45; AEC Category: Q200
signal-integrity model Cap
simulation model Cap
footprint 0805_HV
footprint 0805_HV1
footprint 0805
footprint 0805M
footprint 0805L
pins: 1, 2

## CC0805JRNP09BN471
designator C?  ValueDisplayed: 470pF  (hidden comment: CC0805JRNP09BN471)
CAP, CERM, 470 pF, 50 V,+/- 5%, C0G/NP0, 0805; Manufacturer: Yageo America; Polarized: N; CompType: Capacitor; Value: 470pF; U/M: EA; Cap_F: 0.00000000047; Tolerance_%: 5; VDC_V: 50; Value2: 50V; TaMin_C: -55; TaMax_C: 125; Cap_Case: 0805; SizeArea_mm2: 2.5; SizeAreaWB_mm2: 6.75; SizeX_mm: 2; SizeY_mm: 1.25; SizeZ_mm: 1.45; AEC Category: Q200
signal-integrity model Cap
simulation model Cap
footprint 0805_HV
footprint 0805_HV1
footprint 0805
footprint 0805M
footprint 0805L
pins: 1, 2

## CC0805JRNP09BN560
designator C?  ValueDisplayed: 56pF  (hidden comment: CC0805JRNP09BN560)
CAP, CERM, 56 pF, 50 V,+/- 5%, C0G/NP0, 0805; Manufacturer: Yageo America; Polarized: N; CompType: Capacitor; Value: 56pF; U/M: EA; Cap_F: 0.000000000056; Tolerance_%: 5; VDC_V: 50; Value2: 50V; TaMin_C: -55; TaMax_C: 125; Cap_Case: 0805; SizeArea_mm2: 2.5; SizeAreaWB_mm2: 6.75; SizeX_mm: 2; SizeY_mm: 1.25; SizeZ_mm: 1.45; AEC Category: Q200
signal-integrity model Cap
simulation model Cap
footprint 0805_HV
footprint 0805_HV1
footprint 0805
footprint 0805M
footprint 0805L
pins: 1, 2

## CC0805JRNP09BN561
designator C?  ValueDisplayed: 560pF  (hidden comment: CC0805JRNP09BN561)
CAP, CERM, 560 pF, 50 V,+/- 5%, C0G/NP0, 0805; Manufacturer: Yageo America; Polarized: N; CompType: Capacitor; Value: 560pF; U/M: EA; Cap_F: 0.00000000056; Tolerance_%: 5; VDC_V: 50; Value2: 50V; TaMin_C: -55; TaMax_C: 125; Cap_Case: 0805; SizeArea_mm2: 2.5; SizeAreaWB_mm2: 6.75; SizeX_mm: 2; SizeY_mm: 1.25; SizeZ_mm: 1.45; AEC Category: Q200
signal-integrity model Cap
simulation model Cap
footprint 0805_HV
footprint 0805_HV1
footprint 0805
footprint 0805M
footprint 0805L
pins: 1, 2

## CC0805JRNP09BN680
designator C?  ValueDisplayed: 68pF  (hidden comment: CC0805JRNP09BN680)
CAP, CERM, 68 pF, 50 V,+/- 5%, C0G/NP0, 0805; Manufacturer: Yageo America; Polarized: N; CompType: Capacitor; Value: 68pF; U/M: EA; Cap_F: 0.000000000068; Tolerance_%: 5; VDC_V: 50; Value2: 50V; TaMin_C: -55; TaMax_C: 125; Cap_Case: 0805; SizeArea_mm2: 2.5; SizeAreaWB_mm2: 6.75; SizeX_mm: 2; SizeY_mm: 1.25; SizeZ_mm: 1.45; AEC Category: Q200
signal-integrity model Cap
simulation model Cap
footprint 0805_HV
footprint 0805_HV1
footprint 0805
footprint 0805M
footprint 0805L
pins: 1, 2

## CC0805JRNP09BN681
designator C?  ValueDisplayed: 680pF  (hidden comment: CC0805JRNP09BN681)
CAP, CERM, 680 pF, 50 V,+/- 5%, C0G/NP0, 0805; Manufacturer: Yageo America; Polarized: N; CompType: Capacitor; Value: 680pF; U/M: EA; Cap_F: 0.00000000068; Tolerance_%: 5; VDC_V: 50; Value2: 50V; TaMin_C: -55; TaMax_C: 125; Cap_Case: 0805; SizeArea_mm2: 2.5; SizeAreaWB_mm2: 6.75; SizeX_mm: 2; SizeY_mm: 1.25; SizeZ_mm: 1.45; AEC Category: Q200
signal-integrity model Cap
simulation model Cap
footprint 0805_HV
footprint 0805_HV1
footprint 0805
footprint 0805M
footprint 0805L
pins: 1, 2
